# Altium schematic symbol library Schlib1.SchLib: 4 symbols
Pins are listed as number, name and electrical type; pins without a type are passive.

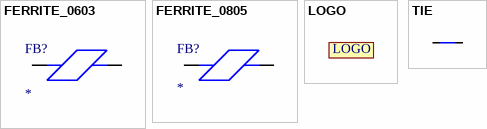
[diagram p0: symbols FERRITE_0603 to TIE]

## FERRITE_0603
designator FB?, comment Ferrite bead Case 0603  (value not drawn)
footprint Chip_0603
pins: 1, 2

## FERRITE_0805
designator FB?, comment Ferrite bead Case 0805  (value not drawn)
footprint CHIP_0805
pins: 1, 2

## LOGO
designator ?
LOGO
footprint LOGO-QTECH

## TIE
designator ?
footprint tie
pins: 1, 2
